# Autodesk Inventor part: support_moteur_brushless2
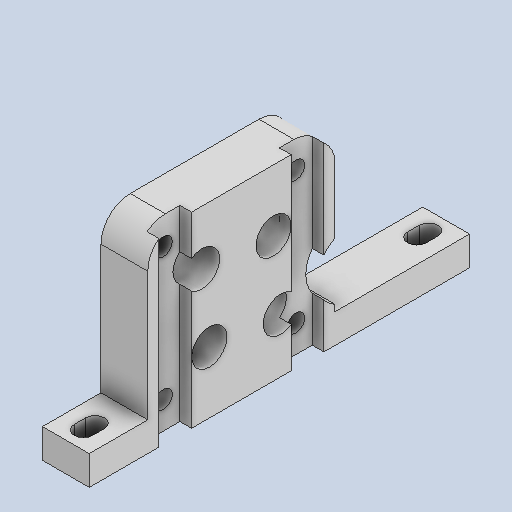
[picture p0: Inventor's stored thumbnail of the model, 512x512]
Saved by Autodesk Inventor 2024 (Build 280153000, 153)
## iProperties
Created: 2022-10
Part Number: support_moteur_brushless2
Material: Générique
Document SubType Name: Modeling
Designer: ropertth
Density: 1 g/cm^3
Appearance: Par défaut
Mass: 7.3531 g
Surface Area: 46.1676 cm^2
Volume: 7.3531 cm^3
Author: ropertth
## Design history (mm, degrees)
sketch "Esquisse1"
  geometry: L1 (0, 0)-(5, 0); L2 (5, 0)-(5, -10); L3 (5, -10)-(32, -10); L4 (32, -10)-(32, -42); L5 (32, -42)-(5, -42); L6 (5, -42)-(5, -65); L7 (5, -65)-(0, -65); L8 (0, -65)-(0, 0)
  constraints: 16 end point, 6 perpendicular, 2 point on line, 1 horizontal
  dimensions: "d0" = 5 distance between parallel lines of L2 L8; "d1" = 32 distance between parallel lines of L4 L8; "d2" = 32 distance of L3.end L4.end; "d3" = 10 distance of L1.end L2.end; "d4" = 65 distance of L7.end L1.start
extrude "Extrusion1" new body sketch "Esquisse1" distance "d5" = 8; taper "d6" = 0 deg
sketch "Esquisse2" dims "d9" = 19
  geometry: L1 (0, 0)-(65, 0) reference; L2 (10, 32)-(10, 5) reference; L3 (26, 16)-(19.282, 22.718); L4 (26, 16)-(20.52, 10.52); C1 r 3 at (19.282, 22.718); C2 r 3 at (20.52, 10.52); C3 r 3 at (31.48, 21.48); C4 r 3 at (32.718, 9.282); A1 r 7.75 centre (26, 16) between (20.52, 10.52) and (20.52, 10.52)
  constraints: 5 centre point, 4 end point, 2 coincident, 2 point on circle, 13 other
  dimensions: "d7" = 16 distance from line of L1 L3.start; "d8" = 16 distance from line of L2 L3.start; "d10" = 45 deg angle of L2 L3; "d11" = 15.5 diameter of A1; "d12" = 45 deg angle of L2 L4; "d13" = 6 diameter of C1; "d14" = 6 diameter of C2; "d31" = 360 deg dimension on L3.start C2.centre (derived); "d35" = 360 deg dimension on L3.start C1.centre (derived)
extrude "Extrusion2" cut sketch "Esquisse2" extent not by distance; stored distance "d15" = 0; taper "d16" = 0 deg
sketch "Esquisse3" dims "d17" = 32
  geometry: L1 (10, 32)-(10, 5) reference; L2 (0, 0)-(65, 0) reference; L3 (26, 16)-(14.686, 27.314); L4 (42, 32)-(10, 32) reference; C1 r 1.5 at (14.686, 27.314); C2 r 1.5 at (14.686, 4.686); C3 r 1.5 at (37.314, 4.686); C4 r 1.5 at (37.314, 27.314)
  constraints: 4 centre point, 2 end point, 1 coincident, 12 other
  dimensions: "d18" = 16 distance from line of L1 L3.start; "d19" = 16 distance from line of L2 L3.start; "d20" = 45 deg angle of L4 L3; "d21" = 3 diameter of C1; "d24" = 360 deg dimension on L3.start C1.centre (derived)
extrude "Extrusion3" cut sketch "Esquisse3" extent not by distance; stored distance "d26" = 0; taper "d27" = 0 deg
fillet "Congé1" dims "d28" = 5
sketch "Esquisse4"
  geometry: L1 (4, 5)-(4, 3); L2 (2.4, 5)-(2.4, 3); L3 (5.6, 3)-(5.6, 5); L4 (0, 0)-(8, 0) reference; L5 (0, 10)-(0, 0) reference; A1 r 1.6 centre (4, 5) between (5.6, 5) and (2.4, 5); A2 r 1.6 centre (4, 3) between (2.4, 3) and (5.6, 3); 1 further point
  constraints: 8 end point, 4 point on circle, 4 tangent, 2 centre point, 1 midpoint, 1 parallel, 1 vertical
  dimensions: "d37" = 3 distance from line of L4 L1.end; "d38" = 2 distance of L1.start L1.end; "d39" = 4 distance between parallel lines of L5 L1; "d40" = 1.6 radius of A2
extrude "Extrusion4" cut sketch "Esquisse4" extent not by distance; stored distance "d41" = 0; taper "d42" = 0 deg
pattern_linear "Réseau rectangulaire1" dims "d45" = 57
sketch "Esquisse5"
  geometry: L1 (11.886, 37.084)-(17.486, 37.084); L2 (17.486, 37.084)-(17.486, -4.581); L3 (17.486, -4.581)-(11.886, -4.581); L4 (11.886, -4.581)-(11.886, 37.084); L5 (34.514, 38.722)-(40.114, 38.722); L6 (40.114, 38.722)-(40.114, -5.31); L7 (40.114, -5.31)-(34.514, -5.31); L8 (34.514, -5.31)-(34.514, 38.722); C1 r 1.5 at (14.686, 27.314) reference; C2 r 1.5 at (37.314, 27.314) reference; 1 further point
  constraints: 16 end point, 4 parallel, 2 horizontal, 2 perpendicular
  dimensions: "d47" = 2.8 distance from line of C1.centre L4; "d48" = 5.6 distance of L1.start L1.end; "d49" = 2.8 distance from line of C2.centre L8; "d50" = 5.6 distance of L5.start L5.end
extrude "Extrusion5" cut sketch "Esquisse5" distance "d51" = 2; taper "d52" = 0 deg
sketch "Esquisse6"
  geometry: L1 (10, 27)-(10, 5) reference; L2 (40.114, 0)-(11.886, 0) reference; C1 r 5.5 at (44.5, 11); 3 further points
  constraints: 1 centre point
  dimensions: "d53" = 34.5 distance from line of L1 C1.centre; "d54" = 11 diameter of C1; "d55" = 11 distance from line of L2 C1.centre
extrude "Extrusion6" cut sketch "Esquisse6" extent not by distance; stored distance "d56" = 0; taper "d57" = 0 deg
node "Solide1"
